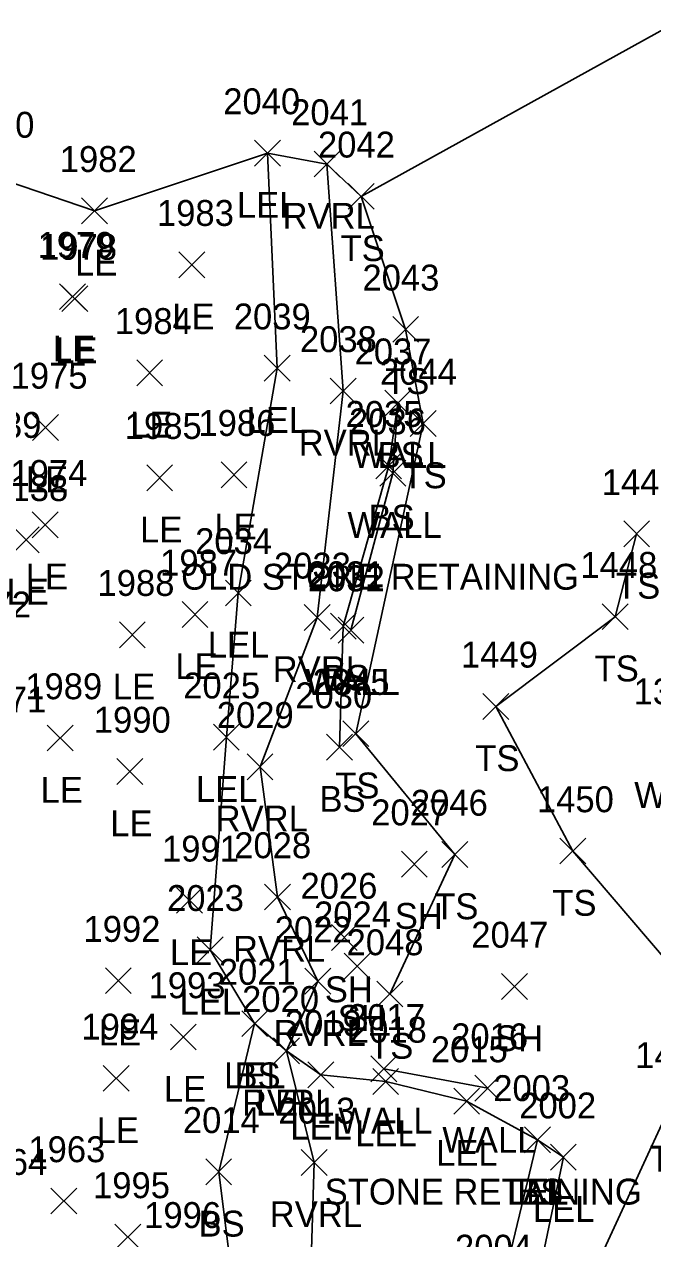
# Model space of a CAD drawing. Extents: x 1638344 to 1639591, y 610835 to 612202.
# Drawn here: x 1638692.3 to 1638740.9, y 611741.3 to 611835.2 of the extents above; entities that cross this region are included whole.
import ezdxf

# ---------------------------------------------------------------- set-up
doc = ezdxf.new("R2010")
doc.units = 0
for name, color, linetype in [('L_A', 7, 'Continuous'), ('L_C', 7, 'Continuous'), ('L_I', 7, 'Continuous'), ('L_TIC', 7, 'Continuous'), ('LARO', 7, 'Continuous'), ('LAWE', 7, 'Continuous'), ('LELB', 7, 'Continuous'), ('LSOGP', 7, 'Continuous'), ('LW', 7, 'Continuous')]:
    doc.layers.add(name, color=color, linetype=linetype)

msp = doc.modelspace()

# ---------------------------------------------------------------- linework, layer by layer
at = {"layer": 'L_TIC'}
for points in [[(1638710.099, 611824.207), (1638712.099, 611826.207)], [(1638712.099, 611824.207), (1638710.099, 611826.207)], [(1638714.698, 611823.36), (1638716.698, 611825.36)], [(1638716.698, 611823.36), (1638714.698, 611825.36)], [(1638717.339, 611820.861), (1638719.339, 611822.861)], [(1638719.339, 611820.861), (1638717.339, 611822.861)], [(1638696.729, 611819.746), (1638698.729, 611821.746)], [(1638698.729, 611819.746), (1638696.729, 611821.746)], [(1638704.243, 611815.579), (1638706.243, 611817.579)], [(1638706.243, 611815.579), (1638704.243, 611817.579)], [(1638695.019, 611813.109), (1638697.019, 611815.109)], [(1638697.019, 611813.109), (1638695.019, 611815.109)], [(1638695.204, 611812.96), (1638697.204, 611814.96)], [(1638697.204, 611812.96), (1638695.204, 611814.96)], [(1638720.779, 611810.585), (1638722.779, 611812.585)], [(1638722.779, 611810.585), (1638720.779, 611812.585)], [(1638710.838, 611807.581), (1638712.838, 611809.581)], [(1638712.838, 611807.581), (1638710.838, 611809.581)], [(1638700.988, 611807.225), (1638702.988, 611809.225)], [(1638702.988, 611807.225), (1638700.988, 611809.225)], [(1638715.942, 611805.826), (1638717.942, 611807.826)], [(1638717.942, 611805.826), (1638715.942, 611807.826)], [(1638720.168, 611804.879), (1638722.168, 611806.879)], [(1638722.168, 611804.879), (1638720.168, 611806.879)], [(1638720.168, 611804.879), (1638722.168, 611806.879)], [(1638722.168, 611804.879), (1638720.168, 611806.879)], [(1638692.928, 611803.004), (1638694.928, 611805.004)], [(1638694.928, 611803.004), (1638692.928, 611805.004)], [(1638722.129, 611803.309), (1638724.129, 611805.309)], [(1638724.129, 611803.309), (1638722.129, 611805.309)], [(1638719.47, 611800.047), (1638721.47, 611802.047)], [(1638721.47, 611800.047), (1638719.47, 611802.047)], [(1638701.756, 611799.117), (1638703.756, 611801.117)], [(1638703.756, 611799.117), (1638701.756, 611801.117)], [(1638707.506, 611799.349), (1638709.506, 611801.349)], [(1638709.506, 611799.349), (1638707.506, 611801.349)], [(1638719.793, 611799.469), (1638721.793, 611801.469)], [(1638721.793, 611799.469), (1638719.793, 611801.469)], [(1638692.914, 611795.485), (1638694.914, 611797.485)], [(1638694.914, 611795.485), (1638692.914, 611797.485)], [(1638738.639, 611794.779), (1638740.639, 611796.779)], [(1638740.639, 611794.779), (1638738.639, 611796.779)], [(1638691.432, 611794.319), (1638693.432, 611796.319)], [(1638693.432, 611794.319), (1638691.432, 611796.319)], [(1638707.84, 611790.218), (1638709.84, 611792.218)], [(1638709.84, 611790.218), (1638707.84, 611792.218)], [(1638704.49, 611788.56), (1638706.49, 611790.56)], [(1638706.49, 611788.56), (1638704.49, 611790.56)], [(1638713.936, 611788.326), (1638715.936, 611790.326)], [(1638715.936, 611788.326), (1638713.936, 611790.326)], [(1638736.982, 611788.384), (1638738.982, 611790.384)], [(1638738.982, 611788.384), (1638736.982, 611790.384)], [(1638699.646, 611786.988), (1638701.646, 611788.988)], [(1638701.646, 611786.988), (1638699.646, 611788.988)], [(1638715.959, 611787.659), (1638717.959, 611789.659)], [(1638717.959, 611787.659), (1638715.959, 611789.659)], [(1638716.553, 611787.345), (1638718.553, 611789.345)], [(1638718.553, 611787.345), (1638716.553, 611789.345)], [(1638727.755, 611781.451), (1638729.755, 611783.451)], [(1638729.755, 611781.451), (1638727.755, 611783.451)], [(1638694.067, 611779.006), (1638696.067, 611781.006)], [(1638696.067, 611779.006), (1638694.067, 611781.006)], [(1638706.917, 611779.066), (1638708.917, 611781.066)], [(1638708.917, 611779.066), (1638706.917, 611781.066)], [(1638716.927, 611779.342), (1638718.927, 611781.342)], [(1638718.927, 611779.342), (1638716.927, 611781.342)], [(1638715.671, 611778.305), (1638717.671, 611780.305)], [(1638717.671, 611778.305), (1638715.671, 611780.305)], [(1638709.522, 611776.786), (1638711.522, 611778.786)], [(1638711.522, 611776.786), (1638709.522, 611778.786)], [(1638699.447, 611776.419), (1638701.447, 611778.419)], [(1638701.447, 611776.419), (1638699.447, 611778.419)], [(1638724.578, 611770.005), (1638726.578, 611772.005)], [(1638726.578, 611770.005), (1638724.578, 611772.005)], [(1638733.71, 611770.274), (1638735.71, 611772.274)], [(1638735.71, 611770.274), (1638733.71, 611772.274)], [(1638721.453, 611769.261), (1638723.453, 611771.261)], [(1638723.453, 611769.261), (1638721.453, 611771.261)], [(1638704.069, 611766.462), (1638706.069, 611768.462)], [(1638706.069, 611766.462), (1638704.069, 611768.462)], [(1638710.865, 611766.72), (1638712.865, 611768.72)], [(1638712.865, 611766.72), (1638710.865, 611768.72)], [(1638716.042, 611763.589), (1638718.042, 611765.589)], [(1638718.042, 611763.589), (1638716.042, 611765.589)], [(1638705.667, 611762.644), (1638707.667, 611764.644)], [(1638707.667, 611762.644), (1638705.667, 611764.644)], [(1638717.037, 611761.376), (1638719.037, 611763.376)], [(1638719.037, 611761.376), (1638717.037, 611763.376)], [(1638698.563, 611760.259), (1638700.563, 611762.259)], [(1638700.563, 611760.259), (1638698.563, 611762.259)], [(1638713.994, 611760.22), (1638715.994, 611762.22)], [(1638715.994, 611760.22), (1638713.994, 611762.22)], [(1638729.196, 611759.808), (1638731.196, 611761.808)], [(1638731.196, 611759.808), (1638729.196, 611761.808)], [(1638719.55, 611759.224), (1638721.55, 611761.224)], [(1638721.55, 611759.224), (1638719.55, 611761.224)], [(1638709.104, 611756.938), (1638711.104, 611758.938)], [(1638711.104, 611756.938), (1638709.104, 611758.938)], [(1638709.104, 611756.938), (1638711.104, 611758.938)], [(1638711.104, 611756.938), (1638709.104, 611758.938)], [(1638703.594, 611755.903), (1638705.594, 611757.903)], [(1638705.594, 611755.903), (1638703.594, 611757.903)], [(1638711.56, 611754.84), (1638713.56, 611756.84)], [(1638713.56, 611754.84), (1638711.56, 611756.84)], [(1638711.56, 611754.84), (1638713.56, 611756.84)], [(1638713.56, 611754.84), (1638711.56, 611756.84)], [(1638719.095, 611753.446), (1638721.095, 611755.446)], [(1638721.095, 611753.446), (1638719.095, 611755.446)], [(1638698.402, 611752.708), (1638700.402, 611754.708)], [(1638700.402, 611752.708), (1638698.402, 611754.708)], [(1638714.218, 611752.975), (1638716.218, 611754.975)], [(1638716.218, 611752.975), (1638714.218, 611754.975)], [(1638719.235, 611752.465), (1638721.235, 611754.465)], [(1638721.235, 611752.465), (1638719.235, 611754.465)], [(1638727.125, 611751.957), (1638729.125, 611753.957)], [(1638729.125, 611751.957), (1638727.125, 611753.957)], [(1638725.496, 611750.953), (1638727.496, 611752.953)], [(1638727.496, 611750.953), (1638725.496, 611752.953)], [(1638730.968, 611747.953), (1638732.968, 611749.953)], [(1638732.968, 611747.953), (1638730.968, 611749.953)], [(1638730.968, 611747.953), (1638732.968, 611749.953)], [(1638732.968, 611747.953), (1638730.968, 611749.953)], [(1638732.976, 611746.615), (1638734.976, 611748.615)], [(1638734.976, 611746.615), (1638732.976, 611748.615)], [(1638713.704, 611746.214), (1638715.704, 611748.214)], [(1638715.704, 611746.214), (1638713.704, 611748.214)], [(1638706.325, 611745.484), (1638708.325, 611747.484)], [(1638708.325, 611745.484), (1638706.325, 611747.484)], [(1638694.349, 611743.232), (1638696.349, 611745.232)], [(1638696.349, 611743.232), (1638694.349, 611745.232)], [(1638699.301, 611740.452), (1638701.301, 611742.452)], [(1638701.301, 611740.452), (1638699.301, 611742.452)]]:
    msp.add_lwpolyline(points, dxfattribs=at)
at = {"layer": 'LARO'}
msp.add_lwpolyline([(1638729.448, 611725.986), (1638733.976, 611747.615), (1638731.968, 611748.953), (1638726.496, 611751.953), (1638720.235, 611753.465), (1638715.218, 611753.975), (1638712.56, 611755.84), (1638710.104, 611757.938), (1638706.667, 611763.644), (1638707.917, 611780.066), (1638708.84, 611791.218), (1638711.838, 611808.581), (1638711.099, 611825.207)], dxfattribs=at)
at = {"layer": 'LAWE'}
msp.add_lwpolyline([(1638671.011, 611601.41), (1638687.934, 611612.159), (1638702.816, 611621.305), (1638722.828, 611637.898), (1638722.694, 611666.366), (1638723.119, 611679.868), (1638719.094, 611692.553), (1638717.187, 611697.341), (1638711.048, 611700.649), (1638718.685, 611716.114), (1638719.359, 611723.061), (1638714.323, 611734.571), (1638714.704, 611747.214), (1638712.56, 611755.84), (1638714.994, 611761.22), (1638711.865, 611767.72), (1638710.522, 611777.786), (1638714.936, 611789.326), (1638716.942, 611806.826), (1638715.698, 611824.36)], dxfattribs=at)
at = {"layer": 'LELB'}
for points in [[(1638718.339, 611821.861), (1638721.779, 611811.585), (1638723.129, 611804.309), (1638717.927, 611780.342), (1638725.578, 611771.005), (1638720.55, 611760.224)], [(1638716.671, 611779.305), (1638716.959, 611788.659), (1638720.47, 611801.047), (1638721.168, 611805.879)], [(1638739.639, 611795.779), (1638737.982, 611789.384), (1638728.755, 611782.451), (1638734.71, 611771.274), (1638743.68, 611760.781), (1638742.219, 611751.498), (1638732.677, 611730.845)], [(1638721.028, 611680.57), (1638715.476, 611695.81), (1638710.279, 611698.997), (1638709.836, 611702.955), (1638709.677, 611706.854), (1638712.785, 611716.361), (1638711.261, 611727.073), (1638708.812, 611734.706), (1638707.325, 611746.484), (1638710.104, 611757.938)], [(1638731.968, 611748.953), (1638729.011, 611736.626), (1638727.673, 611724.518)]]:
    msp.add_lwpolyline(points, dxfattribs=at)
at = {"layer": 'LSOGP'}
msp.add_lwpolyline([(1638742.435, 611835.158), (1638718.339, 611821.861), (1638715.698, 611824.36), (1638711.099, 611825.207), (1638697.729, 611820.746), (1638689.906, 611823.394), (1638677.812, 611825.266), (1638670.59, 611829.25), (1638668.561, 611829.322), (1638661.879, 611825.565), (1638654.744, 611821.976), (1638647.991, 611816.714), (1638639.216, 611819.73), (1638628.579, 611823.011), (1638624.708, 611822.742), (1638622.542, 611822.46), (1638614.597, 611821.058), (1638611.675, 611820.94), (1638608.438, 611821.099), (1638593.01, 611817.319), (1638581.952, 611815.473), (1638593.253, 611782.913), (1638592.058, 611751.785), (1638571.096, 611733.73)], dxfattribs=at)
at = {"layer": 'LW'}
for points in [[(1638717.553, 611788.345), (1638720.793, 611800.469), (1638721.168, 611805.879)], [(1638728.125, 611752.957), (1638720.095, 611754.446)]]:
    msp.add_lwpolyline(points, dxfattribs=at)

# ---------------------------------------------------------------- texts
at = {"layer": 'L_A'}
for s, p in [('LEL', (1638708.737, 611820.207)), ('RVRL', (1638712.265, 611819.36)), ('TS', (1638716.748, 611816.861)), ('LE', (1638696.217, 611815.746)), ('LE', (1638703.731, 611811.579)), ('LE', (1638694.507, 611809.109)), ('LE', (1638694.692, 611808.96)), ('TS', (1638720.188, 611806.585)), ('LE', (1638700.476, 611803.225)), ('LEL', (1638709.476, 611803.581)), ('RVRL', (1638713.509, 611801.826)), ('WALL', (1638717.657, 611800.879)), ('BS', (1638719.609, 611800.879)), ('TS', (1638721.539, 611799.309)), ('LE', (1638692.417, 611799.004)), ('LE', (1638706.994, 611795.349)), ('WALL', (1638717.281, 611795.469)), ('BS', (1638718.911, 611796.047)), ('LE', (1638701.244, 611795.117)), ('LE', (1638692.402, 611791.485)), ('TS', (1638738.048, 611790.779)), ('LE', (1638690.92, 611790.319)), ('LEL', (1638706.478, 611786.218)), ('LE', (1638703.978, 611784.56)), ('RVRL', (1638711.503, 611784.326)), ('TS', (1638736.391, 611784.384)), ('WALL', (1638714.042, 611783.345)), ('BS', (1638715.4, 611783.659)), ('LE', (1638699.134, 611782.988)), ('TS', (1638727.164, 611777.451)), ('LE', (1638693.555, 611775.006)), ('LEL', (1638705.555, 611775.066)), ('TS', (1638716.336, 611775.342)), ('BS', (1638715.112, 611774.305)), ('WDR', (1638739.457, 611774.611)), ('RVRL', (1638707.089, 611772.786)), ('LE', (1638698.936, 611772.419)), ('TS', (1638733.12, 611766.274)), ('SH', (1638720.941, 611765.261)), ('TS', (1638723.988, 611766.005)), ('LE', (1638703.557, 611762.462)), ('RVRL', (1638708.431, 611762.72)), ('SH', (1638715.53, 611759.589)), ('LEL', (1638704.304, 611758.644)), ('SH', (1638716.525, 611757.376)), ('LE', (1638698.051, 611756.259)), ('RVRL', (1638711.561, 611756.22)), ('TS', (1638718.959, 611755.224)), ('SH', (1638728.684, 611755.808)), ('LEL', (1638707.741, 611752.938)), ('BS', (1638708.545, 611752.938)), ('LE', (1638703.082, 611751.903)), ('RVRL', (1638709.127, 611750.84)), ('LEL', (1638710.198, 611750.84)), ('WALL', (1638716.583, 611749.446)), ('LE', (1638697.89, 611748.708)), ('LEL', (1638712.856, 611748.975)), ('LEL', (1638717.873, 611748.465)), ('WALL', (1638724.613, 611747.957)), ('LEL', (1638724.134, 611746.953)), ('TS', (1638740.629, 611746.498)), ('LEL', (1638729.606, 611743.953)), ('BS', (1638730.409, 611743.953)), ('RVRL', (1638711.271, 611742.214)), ('LEL', (1638731.614, 611742.615)), ('BS', (1638705.766, 611741.484))]:
    msp.add_text(s, height=2, dxfattribs=at).set_placement(p)
at = {"layer": 'L_C'}
for s, p in [('OLD STONE RETAINING', (1638704.423, 611791.469)), ('STONE RETAINING', (1638715.518, 611743.957))]:
    msp.add_text(s, height=2, dxfattribs=at).set_placement(p)
at = {"layer": 'L_I'}
for s, p in [('2040', (1638707.674, 611828.207)), ('2041', (1638712.926, 611827.36)), ('1980', (1638687.126, 611826.394)), ('2042', (1638715, 611824.861)), ('1982', (1638695.036, 611823.746)), ('1983', (1638702.55, 611819.579)), ('1979', (1638693.318, 611817.109)), ('1978', (1638693.511, 611816.96)), ('2043', (1638718.44, 611814.585)), ('2039', (1638708.492, 611811.581)), ('1984', (1638699.295, 611811.225)), ('2038', (1638713.604, 611809.826)), ('2037', (1638717.83, 611808.879)), ('2037', (1638717.83, 611808.879)), ('1975', (1638691.235, 611807.004)), ('2044', (1638719.791, 611807.309)), ('2035', (1638717.131, 611804.047)), ('2139', (1638687.668, 611803.201)), ('1985', (1638700.063, 611803.117)), ('1986', (1638705.757, 611803.349)), ('2036', (1638717.4, 611803.469)), ('1974', (1638691.221, 611799.485)), ('2138', (1638689.739, 611798.319)), ('1447', (1638736.946, 611798.779)), ('2034', (1638705.501, 611794.218)), ('1987', (1638702.797, 611792.56)), ('2033', (1638711.598, 611792.326)), ('2031', (1638714.188, 611791.659)), ('1448', (1638735.289, 611792.384)), ('1988', (1638697.953, 611790.988)), ('2032', (1638714.215, 611791.345)), ('1972', (1638686.862, 611789.323)), ('1449', (1638726.054, 611785.451)), ('2045', (1638714.588, 611783.342)), ('1989', (1638692.366, 611783.006)), ('2025', (1638704.579, 611783.066)), ('2030', (1638713.245, 611782.305)), ('1347', (1638739.402, 611782.611)), ('1971', (1638688.049, 611781.982)), ('1990', (1638697.668, 611780.419)), ('2029', (1638707.176, 611780.786)), ('2046', (1638722.185, 611774.005)), ('1450', (1638731.931, 611774.274)), ('2027', (1638719.115, 611773.261)), ('1991', (1638702.943, 611770.462)), ('2028', (1638708.526, 611770.72)), ('2026', (1638713.648, 611767.589)), ('2023', (1638703.328, 611766.644)), ('2024', (1638714.698, 611765.376)), ('1992', (1638696.87, 611764.259)), ('2022', (1638711.655, 611764.22)), ('2047', (1638726.857, 611763.808)), ('2048', (1638717.211, 611763.224)), ('2021', (1638707.332, 611760.938)), ('2021', (1638707.332, 611760.938)), ('1993', (1638701.901, 611759.903)), ('2020', (1638709.135, 611758.84)), ('2020', (1638709.135, 611758.84)), ('2019', (1638712.439, 611756.975)), ('2017', (1638717.323, 611757.446)), ('1994', (1638696.709, 611756.708)), ('2018', (1638717.463, 611756.465)), ('2016', (1638725.298, 611755.957)), ('2015', (1638723.725, 611754.953)), ('1452', (1638739.527, 611754.498)), ('2003', (1638728.55, 611751.953)), ('2003', (1638728.55, 611751.953)), ('2002', (1638730.559, 611750.615)), ('2014', (1638704.553, 611749.484)), ('2013', (1638711.932, 611750.214)), ('1963', (1638692.609, 611747.232)), ('1964', (1638688.117, 611746.249)), ('1995', (1638697.608, 611744.452)), ('1996', (1638701.562, 611742.148)), ('2004', (1638725.594, 611739.626))]:
    msp.add_text(s, height=2, dxfattribs=at).set_placement(p)

doc.saveas('drawing.dxf')
